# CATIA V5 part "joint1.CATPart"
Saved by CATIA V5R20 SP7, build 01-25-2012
Part number: joint1
Bounding box of the stored display mesh (mm): x 165 to 245, y -12 to 12, z -10 to 15
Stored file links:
  D:\thinkmotion-MPB\Dropbox\Pack 1 sylvain\CFAO_2010_yyang\yyang\CFAO_2010_yyang\joint1.CATPart
  D:\thinkmotion-MPB\Dropbox\Pack 1 sylvain\CFAO_2010_yyang\yyang\CFAO_2010_yyang\yyang.CATProduct
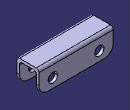
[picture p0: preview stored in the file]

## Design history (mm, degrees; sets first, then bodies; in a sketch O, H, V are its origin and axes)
External parameters (linked from other documents)
  `External.rayon du trou des liaisons` = 5 mm
  `External.distance entre trou et bord` = 10 mm
  External.hauteur = 25 mm
  `External.longeur du joint` = 80 mm
  External.entraxe = 50 mm
  External.epaisseur = 3 mm
  `External.demi-distance entre les des pivot` = 9 mm
Set1
  Plane1: linked copy from another document
  Point1: linked copy from another document
  Point2: linked copy from another document
  Line1: linked copy from another document
  Point3: linked copy from another document
Body1 (main body)
  Sketch1 on Plane1, origin (0, 0, 0), H (-1, 0, 0), V (0, 0, 1)
    circle A1 centre (-230, 0) radius 5
    point P1 (-230, 0)
    reference projected point E1 (-230, 0) from Point1
    reference projected point E2 (-230, 0) from Point1
    line L1 (-245, 15) -> (-165, 15)
    line L2 (-165, 15) -> (-165, 0)
    line L3 (-175, -10) -> (-235, -10)
    line L4 (-245, 0) -> (-245, 15)
    reference projected point E3 (-230, 0) from Point1
    reference projected point E4 (-230, 0) from Point1
    circle A2 centre (-180, 0) radius 5
    point P4 (-180, 0)
    reference projected point E5 (-180, 0) from Point2
    reference projected point E6 (-180, 0) from Point2
    arc A3 centre (-175, 0) radius 10 from (-175, -10) to (-165, 0) ccw
    arc A4 centre (-235, 0) radius 10 from (-235, -10) to (-245, 0) cw
    distance A1 E2 = 5 {= `External.rayon du trou des liaisons`}
    distance L1 L3 = 25 {= External.hauteur}
    distance L3 E3 = 10 {= `External.distance entre trou et bord`}
    distance L4 L2 = 80 {= `External.longeur du joint`}
    distance L4 E4 = 15 {= (`External.longeur du joint`-External.entraxe)/2}
    distance A2 E6 = 5 {= `External.rayon du trou des liaisons`}
    radius A3 = 10 {= `External.distance entre trou et bord`}
    radius A4 = 10 {= `External.distance entre trou et bord`}
    coincidence: P1 E1, P4 E5
    horizontal: L1 H, L3 H
    vertical: L2 V, L4 V
    tangency: A3 L3, A3 L2, A4 L3, A4 L4
  Pad1: profile Sketch1, direction (0, 1, 0), length 12 {= External.epaisseur+`External.demi-distance entre les des pivot`}, mirrored extent
  Shell1: ExtOffset 0, Face (face of Pad1 from Sketch1.L4; face of Pad1 from Sketch1.A1; face of Pad1 from Sketch1.A2), IntOffset 3 {= External.epaisseur}
  Fillet1: radius 3 {= External.epaisseur}, on edge [start face of Pad1 | face of Pad1 from Sketch1.L1]; edge [face of Pad1 from Sketch1.L1 | end face of Pad1]; edge [face of Shell1 | face of Shell1] (x2)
